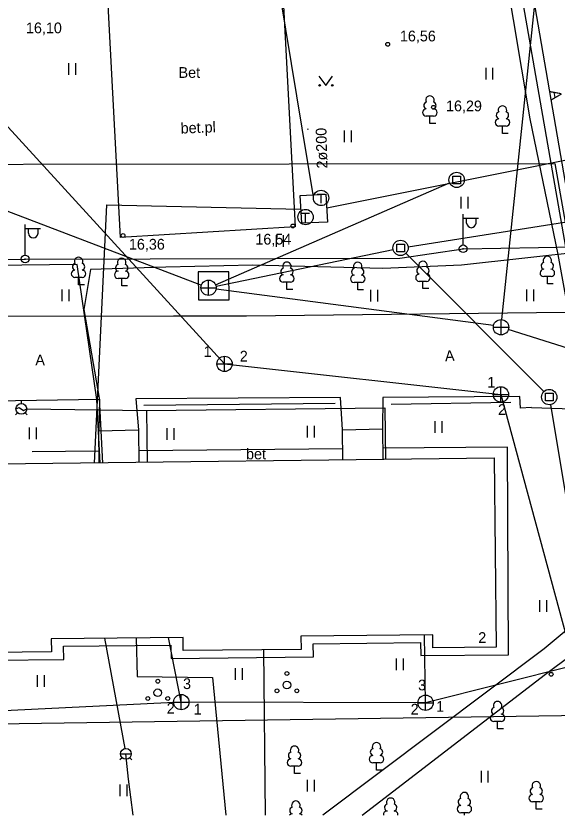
# Model space of a CAD drawing. Extents: x 713540 to 713867, y 6589774 to 6590061.
# Drawn here: x 713665.5 to 713700.8, y 6589774.1 to 6589826.2 of the extents above; entities that cross this region are included whole.
import ezdxf

# ---------------------------------------------------------------- set-up
doc = ezdxf.new("R2010")
doc.units = 0
for name, color, linetype in [('DKAEV', 7, 'Continuous'), ('HALJASTUS', 7, 'Continuous'), ('HOONE', 7, 'Continuous'), ('HOONEDET', 7, 'Continuous'), ('KKAEV', 7, 'Continuous'), ('KORGUS', 7, 'Continuous'), ('KTRASS', 7, 'Continuous'), ('MPKAABEL', 7, 'Continuous'), ('POST', 7, 'Continuous'), ('PUU', 7, 'Continuous'), ('SITRASS', 7, 'Continuous'), ('SKTRASS', 7, 'Continuous'), ('TEE', 7, 'Continuous'), ('TKAEV', 7, 'Continuous'), ('TORU NR', 7, 'Continuous'), ('TTRASS', 7, 'Continuous'), ('VKAEV', 7, 'Continuous'), ('VTRASS', 7, 'Continuous'), ('Слой 1', 7, 'Continuous')]:
    doc.layers.add(name, color=color, linetype=linetype)

msp = doc.modelspace()

# ---------------------------------------------------------------- linework, layer by layer
at = {"layer": 'DKAEV'}
for p, q in [((713693.977, 6589815.253), (713693.977, 6589815.753)), ((713693.977, 6589815.753), (713694.477, 6589815.753)), ((713694.477, 6589815.753), (713694.477, 6589815.253)), ((713694.477, 6589815.253), (713693.977, 6589815.253)), ((713690.315, 6589810.817), (713690.315, 6589811.317)), ((713690.315, 6589811.317), (713690.815, 6589811.317)), ((713690.815, 6589811.317), (713690.815, 6589810.817)), ((713690.815, 6589810.817), (713690.315, 6589810.817)), ((713700.015, 6589801.086), (713700.015, 6589801.586)), ((713700.015, 6589801.586), (713700.515, 6589801.586)), ((713700.515, 6589801.586), (713700.515, 6589801.086)), ((713700.515, 6589801.086), (713700.015, 6589801.086))]:
    msp.add_line(p, q, dxfattribs=at)
for centre in [(713694.227, 6589815.503), (713690.565, 6589811.067), (713700.265, 6589801.336)]:
    msp.add_circle(centre, 0.5, dxfattribs=at)
at = {"layer": 'HALJASTUS'}
for p, q in [((713668.915, 6589823.119), (713668.915, 6589822.358)), ((713669.37, 6589823.119), (713669.37, 6589822.358)), ((713696.119, 6589822.821), (713696.119, 6589822.06)), ((713696.575, 6589822.821), (713696.575, 6589822.06)), ((713685.227, 6589822.277), (713685.69, 6589821.67)), ((713685.69, 6589821.67), (713686.136, 6589822.277)), ((713686.896, 6589818.726), (713686.896, 6589817.965)), ((713687.352, 6589818.726), (713687.352, 6589817.965)), ((713694.508, 6589814.394), (713694.508, 6589813.633)), ((713694.963, 6589814.394), (713694.963, 6589813.633)), ((713682.458, 6589811.897), (713682.458, 6589811.136)), ((713682.913, 6589811.897), (713682.913, 6589811.136)), ((713668.472, 6589808.357), (713668.472, 6589807.596)), ((713668.927, 6589808.357), (713668.927, 6589807.596)), ((713688.612, 6589808.339), (713688.612, 6589807.578)), ((713689.067, 6589808.339), (713689.067, 6589807.578)), ((713698.778, 6589808.355), (713698.778, 6589807.594)), ((713699.233, 6589808.355), (713699.233, 6589807.594)), ((713692.814, 6589799.772), (713692.814, 6589799.011)), ((713693.269, 6589799.772), (713693.269, 6589799.011)), ((713666.348, 6589799.36), (713666.348, 6589798.599)), ((713666.803, 6589799.36), (713666.803, 6589798.599)), ((713675.322, 6589799.315), (713675.322, 6589798.554)), ((713675.778, 6589799.315), (713675.778, 6589798.554)), ((713684.48, 6589799.452), (713684.48, 6589798.691)), ((713684.936, 6589799.452), (713684.936, 6589798.691)), ((713699.624, 6589788.088), (713699.624, 6589787.326)), ((713700.08, 6589788.088), (713700.08, 6589787.326)), ((713690.29, 6589784.287), (713690.29, 6589783.526)), ((713690.745, 6589784.287), (713690.745, 6589783.526)), ((713679.772, 6589783.657), (713679.772, 6589782.896)), ((713680.227, 6589783.657), (713680.227, 6589782.896)), ((713666.867, 6589783.194), (713666.867, 6589782.433)), ((713667.322, 6589783.194), (713667.322, 6589782.433)), ((713695.815, 6589776.953), (713695.815, 6589776.192)), ((713696.27, 6589776.953), (713696.27, 6589776.192)), ((713684.47, 6589776.363), (713684.47, 6589775.602)), ((713684.925, 6589776.363), (713684.925, 6589775.602)), ((713672.265, 6589776.07), (713672.265, 6589775.309)), ((713672.721, 6589776.07), (713672.721, 6589775.309))]:
    msp.add_line(p, q, dxfattribs=at)
for points in [[(713673.823, 6589800.799), (713686.3, 6589800.937)], [(713689.963, 6589800.878), (713697.771, 6589800.994)]]:
    msp.add_lwpolyline(points, dxfattribs=at)
for centre, radius in [((713685.289, 6589821.67), 0.055), ((713686.118, 6589821.67), 0.055), ((713683.156, 6589783.299), 0.125), ((713674.735, 6589782.796), 0.125), ((713683.156, 6589782.549), 0.25), ((713674.735, 6589782.046), 0.25), ((713682.506, 6589782.174), 0.125), ((713683.806, 6589782.174), 0.125), ((713674.085, 6589781.671), 0.125), ((713675.385, 6589781.671), 0.125)]:
    msp.add_circle(centre, radius, dxfattribs=at)
at = {"layer": 'HOONE'}
for p, q in [((713665.836, 6589800.911), (713665.836, 6589801.108)), ((713665.486, 6589800.559), (713665.698, 6589800.665)), ((713665.698, 6589800.665), (713665.975, 6589800.457)), ((713665.589, 6589800.313), (713665.449, 6589800.174)), ((713665.975, 6589800.457), (713666.186, 6589800.563)), ((713666.084, 6589800.313), (713666.223, 6589800.174))]:
    msp.add_line(p, q, dxfattribs=at)
for points in [[(713691.059, 6589811.144), (713725.368, 6589816.545)], [(713678.504, 6589808.667), (713693.768, 6589815.304)], [(713678.535, 6589808.57), (713690.076, 6589810.965)], [(713690.918, 6589810.713), (713699.912, 6589801.69)], [(713708.215, 6589802.384), (713697.597, 6589805.739)], [(713666.186, 6589800.557), (713673.99, 6589800.46), (713689.54, 6589800.63), (713689.583, 6589797.27)], [(713700.347, 6589800.843), (713704.8, 6589774.068)], [(713673.99, 6589800.46), (713674.034, 6589797.069)], [(713670.901, 6589797.029), (713670.879, 6589799.128), (713673.475, 6589799.193), (713673.497, 6589797.062)], [(713686.806, 6589797.234), (713686.786, 6589799.197), (713689.381, 6589799.262), (713689.402, 6589797.268)], [(713631.95, 6589786.08), (713631.9, 6589796.58), (713696.672, 6589797.362), (713696.801, 6589785.016), (713692.677, 6589784.985), (713692.669, 6589785.826), (713684.066, 6589785.737), (713684.075, 6589784.877), (713676.395, 6589784.797), (713676.386, 6589785.657), (713667.783, 6589785.567), (713667.792, 6589784.707), (713660.113, 6589784.627), (713660.104, 6589785.487), (713651.501, 6589785.398), (713651.51, 6589784.538), (713643.83, 6589784.458), (713643.821, 6589785.318), (713635.719, 6589785.234), (713635.728, 6589784.377), (713631.642, 6589784.335), (713631.749, 6589774.068)]]:
    msp.add_lwpolyline(points, dxfattribs=at)
msp.add_circle((713665.836, 6589800.561), 0.35, dxfattribs=at)
at = {"layer": 'KKAEV'}
for p, q in [((713678.046, 6589807.968), (713678.046, 6589808.968)), ((713677.546, 6589808.468), (713678.546, 6589808.468)), ((713697.12, 6589805.39), (713697.12, 6589806.39)), ((713696.62, 6589805.89), (713697.62, 6589805.89)), ((713679.09, 6589802.997), (713679.09, 6589803.997)), ((713678.59, 6589803.497), (713679.59, 6589803.497)), ((713697.109, 6589801.011), (713697.109, 6589802.011)), ((713696.609, 6589801.511), (713697.609, 6589801.511)), ((713676.266, 6589780.934), (713676.266, 6589781.934)), ((713692.201, 6589780.893), (713692.201, 6589781.893)), ((713675.766, 6589781.434), (713676.766, 6589781.434)), ((713691.701, 6589781.393), (713692.701, 6589781.393))]:
    msp.add_line(p, q, dxfattribs=at)
for centre in [(713678.046, 6589808.468), (713697.12, 6589805.89), (713679.09, 6589803.497), (713697.109, 6589801.511), (713676.266, 6589781.434), (713692.201, 6589781.393)]:
    msp.add_circle(centre, 0.5, dxfattribs=at)
at = {"layer": 'KORGUS'}
for centre in [(713689.73, 6589824.35), (713692.72, 6589820.24), (713683.55, 6589812.5), (713672.47, 6589811.88), (713700.39, 6589783.25)]:
    msp.add_circle(centre, 0.125, dxfattribs=at)
at = {"layer": 'KTRASS'}
for p, q in [((713647.455, 6589838.108), (713679.09, 6589803.497)), ((713679.09, 6589803.497), (713697.109, 6589801.511)), ((713697.109, 6589801.511), (713701.893, 6589783.824)), ((713676.266, 6589781.434), (713675.43, 6589785.647)), ((713692.201, 6589781.393), (713692.133, 6589785.82)), ((713701.893, 6589783.824), (713692.201, 6589781.393)), ((713676.266, 6589781.434), (713660.785, 6589780.667)), ((713692.201, 6589781.393), (713676.266, 6589781.434))]:
    msp.add_line(p, q, dxfattribs=at)
msp.add_lwpolyline([(713677.379, 6589807.682), (713679.379, 6589807.685), (713679.376, 6589809.514), (713677.376, 6589809.512), (713677.379, 6589807.682)], dxfattribs=at)
at = {"layer": 'MPKAABEL'}
for points in [[(713633.563, 6589809.916), (713654.618, 6589810.191), (713654.93, 6589810.196), (713666.083, 6589810.341), (713690.526, 6589810.39), (713694.651, 6589811.012), (713704.48, 6589811.17), (713715.623, 6589812.086), (713715.845, 6589812.105), (713721.87, 6589812.6), (713723.29, 6589804.72), (713724.128, 6589800.265), (713724.224, 6589799.756), (713726.25, 6589788.99), (713732.01, 6589789.32)], [(713715.814, 6589812.279), (713715.56, 6589812.268), (713706.735, 6589811.288), (713694.54, 6589809.938), (713689.415, 6589809.721), (713680.928, 6589809.941), (713675.266, 6589809.808), (713670.351, 6589809.668), (713669.919, 6589807.051), (713670.914, 6589801.264), (713671.131, 6589797.032)], [(713670.975, 6589797.03), (713670.762, 6589801.172), (713669.47, 6589809.981), (713655.042, 6589809.82), (713654.683, 6589809.816), (713653.535, 6589809.803), (713639.814, 6589809.192), (713633.345, 6589809.044), (713632.914, 6589808.68)]]:
    msp.add_lwpolyline(points, dxfattribs=at)
at = {"layer": 'POST'}
for p, q in [((713694.651, 6589811.262), (713694.651, 6589813.262)), ((713666.083, 6589810.591), (713666.083, 6589812.591)), ((713694.651, 6589813.012), (713695.651, 6589813.012)), ((713694.878, 6589812.691), (713694.878, 6589813.012)), ((713695.491, 6589812.691), (713695.491, 6589813.012)), ((713666.083, 6589812.341), (713667.083, 6589812.341)), ((713666.309, 6589812.02), (713666.309, 6589812.341)), ((713666.922, 6589812.02), (713666.922, 6589812.341))]:
    msp.add_line(p, q, dxfattribs=at)
for centre, radius in [((713694.651, 6589811.012), 0.25), ((713694.651, 6589811.012), 0.0234), ((713666.083, 6589810.341), 0.25), ((713666.083, 6589810.341), 0.0234)]:
    msp.add_circle(centre, radius, dxfattribs=at)
for centre in [(713695.184, 6589812.691), (713666.616, 6589812.02)]:
    msp.add_arc(centre, 0.306, 180, 0, dxfattribs=at)
at = {"layer": 'PUU'}
for p, q in [((713692.722, 6589819.666), (713692.242, 6589819.666)), ((713692.482, 6589819.191), (713692.482, 6589819.666)), ((713692.862, 6589819.191), (713692.482, 6589819.191)), ((713697.455, 6589819.016), (713696.975, 6589819.016)), ((713697.215, 6589818.541), (713697.215, 6589819.016)), ((713697.595, 6589818.541), (713697.215, 6589818.541)), ((713669.809, 6589809.142), (713669.329, 6589809.142)), ((713669.569, 6589808.667), (713669.569, 6589809.142)), ((713672.621, 6589809.068), (713672.141, 6589809.068)), ((713672.381, 6589808.593), (713672.381, 6589809.068)), ((713700.382, 6589809.196), (713699.902, 6589809.196)), ((713700.142, 6589808.721), (713700.142, 6589809.196)), ((713669.949, 6589808.667), (713669.569, 6589808.667)), ((713672.761, 6589808.593), (713672.381, 6589808.593)), ((713683.394, 6589808.824), (713682.914, 6589808.824)), ((713683.154, 6589808.349), (713683.154, 6589808.824)), ((713688.014, 6589808.809), (713687.534, 6589808.809)), ((713687.774, 6589808.334), (713687.774, 6589808.809)), ((713692.269, 6589808.883), (713691.789, 6589808.883)), ((713692.029, 6589808.408), (713692.029, 6589808.883)), ((713692.409, 6589808.408), (713692.029, 6589808.408)), ((713700.522, 6589808.721), (713700.142, 6589808.721)), ((713683.534, 6589808.349), (713683.154, 6589808.349)), ((713688.154, 6589808.334), (713687.774, 6589808.334)), ((713697.135, 6589780.162), (713696.655, 6589780.162)), ((713696.895, 6589779.687), (713696.895, 6589780.162)), ((713697.275, 6589779.687), (713696.895, 6589779.687)), ((713683.893, 6589777.249), (713683.413, 6589777.249)), ((713683.653, 6589776.774), (713683.653, 6589777.249)), ((713689.239, 6589777.476), (713688.759, 6589777.476)), ((713688.999, 6589777.001), (713688.999, 6589777.476)), ((713684.033, 6589776.774), (713683.653, 6589776.774)), ((713689.379, 6589777.001), (713688.999, 6589777.001)), ((713699.66, 6589774.934), (713699.18, 6589774.934)), ((713699.42, 6589774.459), (713699.42, 6589774.934)), ((713694.969, 6589774.221), (713694.489, 6589774.221)), ((713694.729, 6589774.068), (713694.729, 6589774.221)), ((713699.8, 6589774.459), (713699.42, 6589774.459))]:
    msp.add_line(p, q, dxfattribs=at)
for centre, radius, start, end in [((713692.482, 6589820.711), 0.277, 332.5799, 207.4201), ((713692.312, 6589820.364), 0.233, 109.0217, 253.1415), ((713692.652, 6589820.364), 0.233, 286.8508, 70.9859), ((713692.245, 6589819.904), 0.238, 90.0016, 269.3953), ((713692.72, 6589819.904), 0.238, 270.6047, 89.9984), ((713697.045, 6589819.713), 0.233, 109.0217, 253.1415), ((713697.215, 6589820.061), 0.277, 332.5799, 207.4201), ((713697.386, 6589819.713), 0.233, 286.8508, 70.9859), ((713696.978, 6589819.253), 0.238, 90.0016, 269.3953), ((713697.453, 6589819.253), 0.238, 270.6047, 89.9984), ((713700.142, 6589810.241), 0.277, 332.5799, 207.4201), ((713669.399, 6589809.839), 0.233, 109.0217, 253.1415), ((713669.569, 6589810.187), 0.277, 332.5799, 207.4201), ((713669.739, 6589809.839), 0.233, 286.8508, 70.9859), ((713672.211, 6589809.765), 0.233, 109.0217, 253.1415), ((713672.381, 6589810.113), 0.277, 332.5799, 207.4201), ((713672.551, 6589809.765), 0.233, 286.8508, 70.9859), ((713683.154, 6589809.869), 0.277, 332.5799, 207.4201), ((713687.774, 6589809.854), 0.277, 332.5799, 207.4201), ((713692.029, 6589809.928), 0.277, 332.5799, 207.4201), ((713699.972, 6589809.894), 0.233, 109.0217, 253.1415), ((713700.312, 6589809.894), 0.233, 286.8508, 70.9859), ((713669.331, 6589809.379), 0.238, 90.0016, 269.3953), ((713669.806, 6589809.379), 0.238, 270.6047, 89.9984), ((713672.143, 6589809.305), 0.238, 90.0016, 269.3953), ((713672.618, 6589809.305), 0.238, 270.6047, 89.9984), ((713682.984, 6589809.522), 0.233, 109.0217, 253.1415), ((713683.324, 6589809.522), 0.233, 286.8508, 70.9859), ((713687.604, 6589809.506), 0.233, 109.0217, 253.1415), ((713687.944, 6589809.506), 0.233, 286.8508, 70.9859), ((713691.859, 6589809.58), 0.233, 109.0217, 253.1415), ((713692.199, 6589809.58), 0.233, 286.8508, 70.9859), ((713699.904, 6589809.433), 0.238, 90.0016, 269.3953), ((713700.379, 6589809.433), 0.238, 270.6047, 89.9984), ((713682.916, 6589809.062), 0.238, 90.0016, 269.3953), ((713683.391, 6589809.062), 0.238, 270.6047, 89.9984), ((713687.537, 6589809.046), 0.238, 90.0016, 269.3953), ((713688.011, 6589809.046), 0.238, 270.6047, 89.9984), ((713691.792, 6589809.12), 0.238, 90.0016, 269.3953), ((713692.267, 6589809.12), 0.238, 270.6047, 89.9984), ((713696.895, 6589781.207), 0.277, 332.5799, 207.4201), ((713696.725, 6589780.86), 0.233, 109.0217, 253.1415), ((713697.065, 6589780.86), 0.233, 286.8508, 70.9859), ((713696.658, 6589780.4), 0.238, 90.0016, 269.3953), ((713697.133, 6589780.4), 0.238, 270.6047, 89.9984), ((713688.999, 6589778.521), 0.277, 332.5799, 207.4201), ((713683.653, 6589778.294), 0.277, 332.5799, 207.4201), ((713688.829, 6589778.173), 0.233, 109.0217, 253.1415), ((713689.169, 6589778.173), 0.233, 286.8508, 70.9859), ((713683.415, 6589777.487), 0.238, 90.0016, 269.3953), ((713683.483, 6589777.947), 0.233, 109.0217, 253.1415), ((713683.823, 6589777.947), 0.233, 286.8508, 70.9859), ((713683.89, 6589777.487), 0.238, 270.6047, 89.9984), ((713688.761, 6589777.713), 0.238, 90.0016, 269.3953), ((713689.236, 6589777.713), 0.238, 270.6047, 89.9984), ((713699.42, 6589775.979), 0.277, 332.5799, 207.4201), ((713699.25, 6589775.631), 0.233, 109.0217, 253.1415), ((713699.59, 6589775.631), 0.233, 286.8508, 70.9859), ((713689.922, 6589774.9), 0.277, 332.5799, 207.4201), ((713694.558, 6589774.918), 0.233, 109.0217, 253.1415), ((713694.729, 6589775.266), 0.277, 332.5799, 207.4201), ((713694.899, 6589774.918), 0.233, 286.8508, 70.9859), ((713699.182, 6589775.171), 0.238, 90.0016, 269.3953), ((713699.657, 6589775.171), 0.238, 270.6047, 89.9984), ((713683.57, 6589774.361), 0.233, 109.0217, 253.1415), ((713683.74, 6589774.709), 0.277, 332.5799, 207.4201), ((713683.91, 6589774.361), 0.233, 286.8508, 70.9859), ((713689.752, 6589774.553), 0.233, 109.0217, 253.1415), ((713690.092, 6589774.553), 0.233, 286.8508, 70.9859), ((713694.491, 6589774.458), 0.238, 90.0016, 269.3953), ((713694.966, 6589774.458), 0.238, 270.6047, 89.9984), ((713683.502, 6589773.901), 0.238, 90.0016, 135.2643), ((713683.977, 6589773.901), 0.238, 44.7357, 89.9984), ((713689.684, 6589774.093), 0.238, 90.0016, 185.8734), ((713690.159, 6589774.093), 0.238, 354.1266, 89.9984)]:
    msp.add_arc(centre, radius, start, end, dxfattribs=at)
at = {"layer": 'SITRASS'}
for points in [[(713692.355, 6589841.896), (713696.3, 6589835.59), (713698.99, 6589819.49), (713700.82, 6589810.63), (713702.44, 6589801.79), (713704.26, 6589791.98), (713706.2, 6589780.63), (713707.441, 6589774.068)], [(713673.314, 6589785.625), (713673.4, 6589783.1), (713678.3, 6589783.03), (713679.175, 6589774.068)], [(713681.636, 6589784.851), (713681.748, 6589774.068)]]:
    msp.add_lwpolyline(points, dxfattribs=at)
at = {"layer": 'SKTRASS'}
for points in [[(713697.172, 6589806.387), (713700.379, 6589836.974)], [(713649.892, 6589819.209), (713677.579, 6589808.646)], [(713678.542, 6589808.403), (713696.639, 6589806.026)]]:
    msp.add_lwpolyline(points, dxfattribs=at)
at = {"layer": 'TEE'}
for points in [[(713696.453, 6589839.015), (713701.863, 6589808.006), (713701.336, 6589806.867)], [(713682.821, 6589828.937), (713683.689, 6589812.444), (713672.306, 6589811.743), (713671.438, 6589828.172), (713682.821, 6589828.937)], [(713558.242, 6589774.068), (713558, 6589777.11), (713557.55, 6589780.29), (713553.14, 6589780.32), (713553.11, 6589780.41), (713552.46, 6589795.14), (713552.58, 6589795.15), (713564.88, 6589795.29), (713582.17, 6589795.52), (713594.953, 6589795.665), (713611.695, 6589795.898), (713616.978, 6589806.321), (713631.194, 6589806.435), (713655.999, 6589806.607), (713675.755, 6589806.635), (713680.518, 6589806.639), (713701.336, 6589806.867)], [(713657.36, 6589798.69), (713657.24, 6589800.98), (713670.924, 6589801.203), (713670.879, 6589799.128)], [(713686.786, 6589799.197), (713686.658, 6589801.309), (713673.295, 6589801.216), (713673.475, 6589799.193)], [(713699.112, 6589800.645), (713698.387, 6589800.606), (713698.338, 6589801.373), (713689.419, 6589801.297), (713689.381, 6589799.262)], [(713699.112, 6589800.645), (713703.116, 6589800.535), (713705.247, 6589789.32), (713699.927, 6589784.903), (713685.509, 6589774.068)], [(713632.549, 6589774.068), (713632.447, 6589783.843), (713636.533, 6589783.886), (713636.524, 6589784.742), (713643.027, 6589784.81), (713643.036, 6589783.95), (713652.315, 6589784.046), (713652.306, 6589784.906), (713659.309, 6589784.979), (713659.318, 6589784.119), (713668.598, 6589784.216), (713668.589, 6589785.076), (713675.591, 6589785.148), (713675.6, 6589784.288), (713684.88, 6589784.385), (713684.871, 6589785.245), (713691.874, 6589785.318), (713691.883, 6589784.479), (713697.606, 6589784.522), (713697.542, 6589798.077), (713689.395, 6589797.992)], [(713670.893, 6589797.8), (713666.544, 6589797.754)], [(713686.799, 6589797.965), (713673.489, 6589797.827)], [(713688.057, 6589774.068), (713700.032, 6589783.261), (713705.354, 6589787.24), (713707.729, 6589774.068)]]:
    msp.add_lwpolyline(points, dxfattribs=at)
at = {"layer": 'TKAEV'}
for p, q in [((713685.131, 6589814.576), (713685.631, 6589814.576)), ((713685.381, 6589813.976), (713685.381, 6589814.576)), ((713684.122, 6589813.329), (713684.622, 6589813.329)), ((713684.372, 6589812.729), (713684.372, 6589813.329))]:
    msp.add_line(p, q, dxfattribs=at)
for centre in [(713685.381, 6589814.326), (713684.372, 6589813.079)]:
    msp.add_circle(centre, 0.5, dxfattribs=at)
at = {"layer": 'TTRASS'}
for points in [[(713668.38, 6589851.34), (713670.97, 6589836.31), (713680.94, 6589838.27), (713684.857, 6589814.536)], [(713719.43, 6589820.41), (713714.539, 6589819.43), (713714.316, 6589819.386), (713685.752, 6589813.666)], [(713684.5, 6589818.85), (713684.513, 6589818.786)], [(713684.012, 6589814.496), (713685.702, 6589814.576), (713685.802, 6589812.756), (713684.122, 6589812.686), (713684.012, 6589814.496)], [(713670.612, 6589797.025), (713671.42, 6589813.88), (713684.067, 6589813.591)]]:
    msp.add_lwpolyline(points, dxfattribs=at)
at = {"layer": 'VKAEV'}
for p, q in [((713672.409, 6589777.808), (713672.269, 6589777.668)), ((713672.306, 6589778.055), (713673.006, 6589778.055)), ((713672.903, 6589777.808), (713673.043, 6589777.668))]:
    msp.add_line(p, q, dxfattribs=at)
msp.add_circle((713672.656, 6589778.055), 0.35, dxfattribs=at)
at = {"layer": 'VTRASS'}
for points in [[(713708.725, 6589774.068), (713707.065, 6589783.601), (713705.018, 6589794.55), (713701.84, 6589812.321), (713699.235, 6589827.436), (713699.875, 6589827.579), (713696.888, 6589845.261), (713694.289, 6589860.829), (713691.539, 6589877.243), (713690.275, 6589883.906), (713690.135, 6589884.996), (713689.231, 6589889.843), (713687.737, 6589897.698), (713684.897, 6589913.25), (713684.491, 6589918.952), (713684.308, 6589921.181)], [(713671.268, 6589785.603), (713672.593, 6589778.399)], [(713673.118, 6589774.068), (713672.818, 6589776.407), (713672.656, 6589778.055)]]:
    msp.add_lwpolyline(points, dxfattribs=at)
at = {"layer": 'Слой 1'}
msp.add_lwpolyline([(713706.95, 6589780.62), (713633.23, 6589779.53), (713631.93, 6589779.47), (713632.04, 6589786.08), (713631.13, 6589786.14), (713631.13, 6589806.31), (713631.28, 6589816.48), (713700.64, 6589816.58)], close=True, dxfattribs=at)

# ---------------------------------------------------------------- texts
at = {"layer": 'HOONE'}
msp.add_text('2', height=0.7, rotation=0.1784, dxfattribs=at).set_placement((713695.636, 6589785.295))
at = {"layer": 'HOONEDET'}
msp.add_text('bet.pl', height=0.7, rotation=2.1288, dxfattribs=at).set_placement((713676.238, 6589818.525))
msp.add_text('bet', height=0.7, dxfattribs=at).set_placement((713680.491, 6589797.276))
at = {"layer": 'KORGUS'}
for s, p in [('16,10', (713666.135, 6589825.07)), ('16,56', (713690.525, 6589824.54)), ('16,29', (713693.532, 6589819.98)), ('16,36', (713672.85, 6589810.955)), ('16,54', (713681.098, 6589811.285))]:
    msp.add_text(s, height=0.7, dxfattribs=at).set_placement(p)
at = {"layer": 'TEE'}
msp.add_text('Bet', height=0.7, dxfattribs=at).set_placement((713676.09, 6589822.16))
for rotation, p in [(280.1296, (713700.318, 6589821.304)), (2.8752, (713693.481, 6589803.67)), (0.4061, (713666.749, 6589803.406))]:
    msp.add_text('A', height=0.7, rotation=rotation, dxfattribs=at).set_placement(p)
at = {"layer": 'TORU NR'}
msp.add_text('2ø200', height=0.7, rotation=91.609, dxfattribs=at).set_placement((713685.802, 6589816.258))
for s, p in [('1', (713677.722, 6589803.956)), ('2', (713680.082, 6589803.655)), ('1', (713696.227, 6589801.949)), ('2', (713696.925, 6589800.169)), ('3', (713676.381, 6589782.286)), ('3', (713691.711, 6589782.2)), ('2', (713675.319, 6589780.687)), ('1', (713677.078, 6589780.623)), ('2', (713691.228, 6589780.623)), ('1', (713692.891, 6589780.805))]:
    msp.add_text(s, height=0.7, dxfattribs=at).set_placement(p)

doc.saveas('drawing.dxf')
